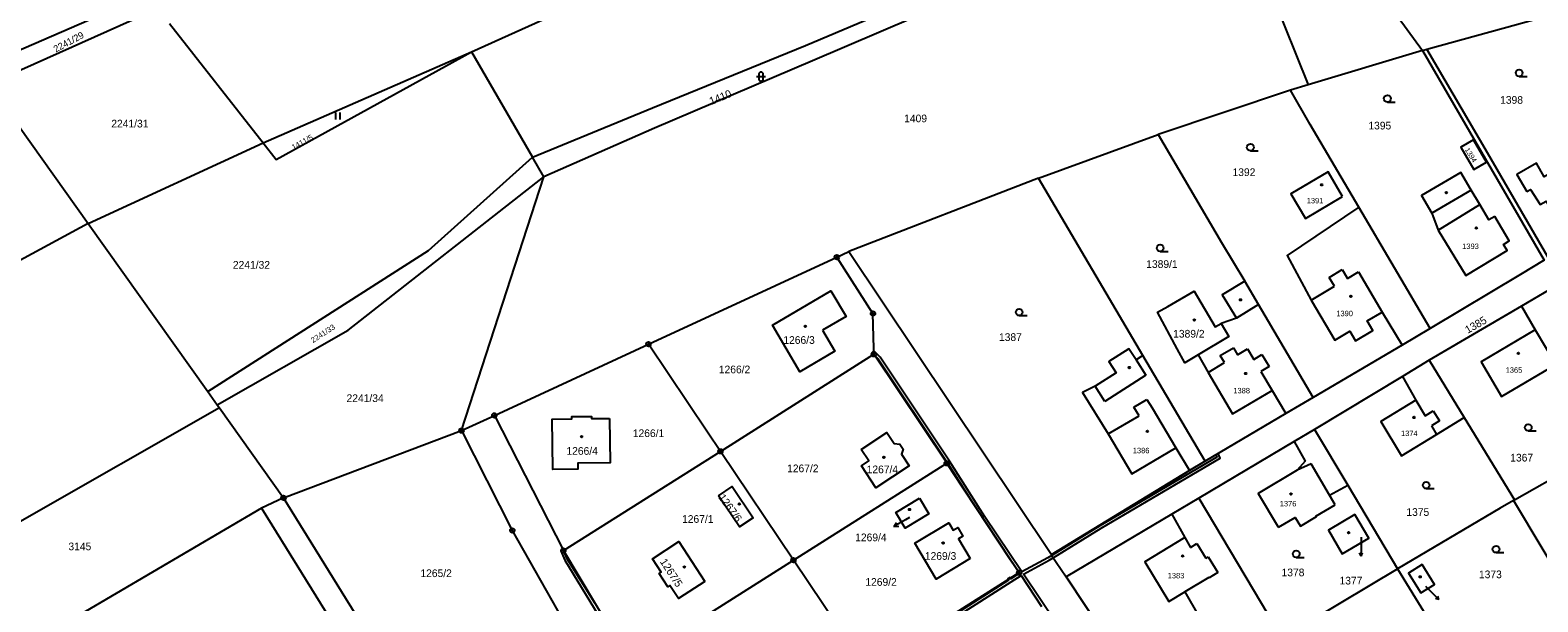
# Model space of a CAD drawing. Extents: x -504988 to -494607, y -1123820 to -1114018.
# Drawn here: x -498445.5 to -498111.8, y -1119267 to -1119140.5 of the extents above; entities that cross this region are included whole.
import ezdxf

# ---------------------------------------------------------------- set-up
doc = ezdxf.new("R2010")
doc.units = 0
for name, color, linetype in [('Hranice parcel', 7, 'Continuous'), ('Parcelní čísla', 7, 'Continuous'), ('Pop  PČ popisy', 7, 'Continuous'), ('Vnitřní kresba', 7, 'Continuous'), ('Věcná břemena k části', 7, 'Continuous'), ('Značky bodu BP', 7, 'Continuous'), ('Značky budov', 7, 'Continuous'), ('Značky kultur', 7, 'Continuous')]:
    doc.layers.add(name, color=color, linetype=linetype)

msp = doc.modelspace()

# ---------------------------------------------------------------- linework, layer by layer
at = {"layer": 'Hranice parcel'}
for p, q in [((-498176.47, -1119118.03), (-498162.61, -1119152.61)), ((-498157.48, -1119117.49), (-498137.28, -1119144.99)), ((-498419.61, -1119132.7), (-498457.09, -1119149)), ((-498454.64, -1119152.44), (-498417.24, -1119135.72)), ((-498414.66, -1119139.01), (-498393.92, -1119165.45)), ((-498136.33, -1119144.7), (-498111.4, -1119137.86)), ((-498393.92, -1119165.45), (-498347.84, -1119145.3)), ((-498347.84, -1119145.3), (-498334.3, -1119168.63)), ((-498137.28, -1119144.99), (-498162.61, -1119152.61)), ((-498137.28, -1119144.99), (-498136.33, -1119144.7)), ((-498454.64, -1119152.44), (-498432.67, -1119183.28)), ((-498166.51, -1119153.79), (-498195.79, -1119163.6)), ((-498162.61, -1119152.61), (-498166.51, -1119153.79)), ((-498222.34, -1119173.27), (-498195.79, -1119163.6)), ((-498432.67, -1119183.28), (-498393.92, -1119165.45)), ((-498331.79, -1119172.96), (-498334.3, -1119168.63)), ((-498350.01, -1119229.11), (-498331.79, -1119172.96)), ((-498222.34, -1119173.27), (-498264.28, -1119189.49)), ((-498199.2, -1119212.51), (-498222.34, -1119173.27)), ((-498135.6, -1119206.51), (-498151.42, -1119179.68)), ((-498432.67, -1119183.28), (-498406.17, -1119220.48)), ((-498266.95, -1119190.72), (-498264.28, -1119189.49)), ((-498308.62, -1119209.98), (-498266.95, -1119190.72)), ((-498258.94, -1119203.22), (-498266.95, -1119190.72)), ((-498109.12, -1119197.88), (-498115.41, -1119201.58)), ((-498115.41, -1119201.58), (-498135.81, -1119213.56)), ((-498135.6, -1119206.51), (-498141.8, -1119210.18)), ((-498342.74, -1119225.75), (-498308.62, -1119209.98)), ((-498141.8, -1119210.18), (-498161.49, -1119221.82)), ((-498292.71, -1119233.7), (-498258.74, -1119212.23)), ((-498242.62, -1119236.35), (-498258.74, -1119212.23)), ((-498185.45, -1119235.85), (-498199.2, -1119212.51)), ((-498135.81, -1119213.56), (-498141.77, -1119217.14)), ((-498135.81, -1119213.56), (-498128.09, -1119226.19)), ((-498141.77, -1119217.14), (-498161.24, -1119228.84)), ((-498406.17, -1119220.48), (-498404.1, -1119223.38)), ((-498404.1, -1119223.38), (-498403.59, -1119224.1)), ((-498161.49, -1119221.82), (-498167.53, -1119225.36)), ((-498403.59, -1119224.1), (-498389.42, -1119243.99)), ((-498350.01, -1119229.11), (-498342.74, -1119225.75)), ((-498342.74, -1119225.75), (-498327.47, -1119255.66)), ((-498167.53, -1119225.36), (-498185.45, -1119235.85)), ((-498128.09, -1119226.19), (-498116.93, -1119244.45)), ((-498389.42, -1119243.99), (-498350.01, -1119229.11)), ((-498161.24, -1119228.84), (-498165.72, -1119231.5)), ((-498161.24, -1119228.84), (-498153.87, -1119241.2)), ((-498327.47, -1119255.66), (-498292.71, -1119233.7)), ((-498276.55, -1119257.79), (-498292.71, -1119233.7)), ((-498165.72, -1119231.5), (-498186.82, -1119244.07)), ((-498276.55, -1119257.79), (-498242.62, -1119236.35)), ((-498185.45, -1119235.85), (-498188.86, -1119237.93)), ((-498116.93, -1119244.45), (-498104.11, -1119237.11)), ((-498188.86, -1119237.93), (-498219.49, -1119256.58)), ((-498153.87, -1119241.2), (-498142.82, -1119259.73)), ((-498394.29, -1119246.3), (-498477.41, -1119294.96)), ((-498389.42, -1119243.99), (-498394.29, -1119246.3)), ((-498394.29, -1119246.3), (-498375.52, -1119276.48)), ((-498360.07, -1119291.3), (-498389.42, -1119243.99)), ((-498186.82, -1119244.07), (-498192.79, -1119247.61)), ((-498186.82, -1119244.07), (-498169.68, -1119272.79)), ((-498116.93, -1119244.45), (-498117.19, -1119244.61)), ((-498117.19, -1119244.61), (-498098.47, -1119275.83)), ((-498192.79, -1119247.61), (-498216.21, -1119261.47)), ((-498219.49, -1119256.58), (-498216.21, -1119261.47)), ((-498312.55, -1119280.54), (-498276.55, -1119257.79)), ((-498168.4, -1119274.94), (-498142.82, -1119259.73)), ((-498142.82, -1119259.73), (-498133.3, -1119275.24)), ((-498216.21, -1119261.47), (-498196.16, -1119291.56))]:
    msp.add_line(p, q, dxfattribs=at)
for points in [[(-498347.84, -1119145.3), (-498307.68, -1119127.2), (-498226.19, -1119098.54), (-498200.12, -1119089.51)], [(-498334.3, -1119168.63), (-498307.73, -1119157.69), (-498273.85, -1119143.89), (-498220.78, -1119121.39), (-498189.63, -1119116.18)], [(-498176.47, -1119118.03), (-498188.44, -1119118.94), (-498220.2, -1119124.93), (-498272.34, -1119147.33), (-498307.3, -1119162.21), (-498331.79, -1119172.96)], [(-498393.92, -1119165.45), (-498391.06, -1119169.1), (-498347.84, -1119145.3)], [(-498137.28, -1119144.99), (-498110.37, -1119191.37), (-498115.64, -1119194.57), (-498135.6, -1119206.51)], [(-498087.55, -1119177.87), (-498109.51, -1119190.84), (-498122.93, -1119167.67), (-498136.33, -1119144.7)], [(-498151.42, -1119179.68), (-498162.19, -1119161.42), (-498166.51, -1119153.79)], [(-498195.79, -1119163.6), (-498181.78, -1119187.48), (-498176.65, -1119196.07)], [(-498123.17, -1119169.72), (-498126.02, -1119164.81), (-498128.8, -1119166.42), (-498125.95, -1119171.34), (-498123.17, -1119169.72)], [(-498406.17, -1119220.48), (-498357.36, -1119189.26), (-498334.3, -1119168.63)], [(-498114.25, -1119176.23), (-498113.43, -1119175.76), (-498111.24, -1119179.09), (-498109.97, -1119178.33), (-498106.89, -1119183.53), (-498098.66, -1119178.66), (-498104.13, -1119169.37), (-498110.38, -1119172.93), (-498112.07, -1119169.96), (-498116.41, -1119172.43), (-498114.25, -1119176.23)], [(-498404.1, -1119223.38), (-498375.11, -1119206.88), (-498331.79, -1119172.96)], [(-498154.99, -1119177.33), (-498158.18, -1119171.89), (-498166.42, -1119176.73), (-498163.22, -1119182.16), (-498154.99, -1119177.33)], [(-498121.31, -1119181.74), (-498122.6, -1119182.5), (-498124.6, -1119179.1), (-498126.55, -1119175.93), (-498128.85, -1119171.99), (-498137.56, -1119177.06), (-498135.26, -1119181), (-498133.88, -1119184.74), (-498127.74, -1119194.78), (-498118.6, -1119189.3), (-498119.42, -1119187.91), (-498118.13, -1119187.15), (-498121.31, -1119181.74)], [(-498151.42, -1119179.68), (-498167.29, -1119190.35), (-498161.98, -1119200.24), (-498156.72, -1119209.1), (-498153.4, -1119207.14), (-498152.14, -1119209.27), (-498148.29, -1119207), (-498149.56, -1119204.86), (-498146.23, -1119202.89), (-498141.8, -1119210.18)], [(-498432.67, -1119183.28), (-498599.02, -1119273.35), (-498667.99, -1119331.88), (-498738.66, -1119434), (-498809.33, -1119536.13), (-498929.21, -1119599.31)], [(-498264.28, -1119189.49), (-498219.6, -1119256.32), (-498219.49, -1119256.58)], [(-498176.65, -1119196.07), (-498181.64, -1119199.09), (-498178.51, -1119204.27), (-498181.88, -1119205.43)], [(-498161.49, -1119221.82), (-498173.59, -1119201.21), (-498176.65, -1119196.07)], [(-498270.12, -1119206.9), (-498267.37, -1119211.56), (-498275.16, -1119216.08), (-498281.21, -1119205.75), (-498268.27, -1119198.19), (-498264.91, -1119203.9), (-498270.12, -1119206.9)], [(-498186.93, -1119212.34), (-498189.92, -1119214.13), (-498191.63, -1119211.02), (-498195.94, -1119202.94), (-498193.68, -1119201.66), (-498187.84, -1119198.24), (-498183.2, -1119206.17), (-498181.88, -1119205.43)], [(-498258.74, -1119212.23), (-498258.77, -1119210.96), (-498258.94, -1119203.22)], [(-498115.41, -1119201.58), (-498112.37, -1119206.82), (-498124.35, -1119213.92), (-498119.8, -1119221.59), (-498107.82, -1119214.5), (-498105.78, -1119213.05), (-498106.4, -1119212.03), (-498103.25, -1119210.13), (-498102.16, -1119209.6)], [(-498181.88, -1119205.43), (-498180.18, -1119208.28), (-498186.93, -1119212.34)], [(-498292.71, -1119233.7), (-498295.55, -1119229.46), (-498308.62, -1119209.98)], [(-498199.2, -1119212.51), (-498200.7, -1119213.47), (-498202.3, -1119210.99), (-498206.73, -1119213.85), (-498205.13, -1119216.33), (-498209.76, -1119219.31), (-498212.55, -1119220.67), (-498206.87, -1119229.86), (-498201.63, -1119238.68), (-498191.94, -1119232.92), (-498188.86, -1119237.93)], [(-498186.93, -1119212.34), (-498184.78, -1119216.23), (-498179.34, -1119225.4), (-498170.59, -1119220.21), (-498167.53, -1119225.36)], [(-498141.77, -1119217.14), (-498138.78, -1119222.41), (-498146.53, -1119227.13), (-498141.94, -1119234.69), (-498134.18, -1119229.98), (-498128.09, -1119226.19)], [(-498403.59, -1119224.1), (-498492.01, -1119274.49), (-498477.41, -1119294.96)], [(-498317.25, -1119226.42), (-498317.15, -1119236.26), (-498324.29, -1119236.35), (-498324.27, -1119237.65), (-498329.8, -1119237.73), (-498329.93, -1119226.58), (-498325.59, -1119226.53), (-498325.59, -1119226.02), (-498321.25, -1119225.98), (-498321.24, -1119226.47), (-498317.25, -1119226.42)], [(-498350.01, -1119229.11), (-498338.78, -1119251.2), (-498327.52, -1119271.11)], [(-498261.55, -1119233.32), (-498255.84, -1119229.52), (-498254.23, -1119231.94), (-498252.99, -1119232.14), (-498252.29, -1119233.2), (-498252.62, -1119234.36), (-498250.94, -1119236.89), (-498258.29, -1119241.79), (-498261.51, -1119236.89), (-498259.88, -1119235.82), (-498261.55, -1119233.32)], [(-498165.72, -1119231.5), (-498163.27, -1119235.88), (-498165.08, -1119237.88), (-498173.68, -1119243.04), (-498169.39, -1119250.2), (-498169.19, -1119250.51)], [(-498228.47, -1119257.7), (-498241.27, -1119238.4), (-498242.62, -1119236.35)], [(-498293.15, -1119243.55), (-498290.11, -1119241.5), (-498285.47, -1119248.39), (-498288.5, -1119250.43), (-498293.15, -1119243.55)], [(-498156.63, -1119245.5), (-498157.89, -1119243.36), (-498153.87, -1119241.2)], [(-498248.66, -1119244.09), (-498246.58, -1119247.53), (-498251.85, -1119250.71), (-498253.9, -1119247.24), (-498248.66, -1119244.09)], [(-498169.19, -1119250.51), (-498165.46, -1119248.36), (-498164.32, -1119250.25), (-498160.8, -1119248.15), (-498160.89, -1119248.03), (-498156.63, -1119245.5)], [(-498117.19, -1119244.61), (-498120.09, -1119246.31), (-498142.82, -1119259.73)], [(-498237.41, -1119257.41), (-498244.94, -1119261.95), (-498249.69, -1119254.04), (-498242.14, -1119249.52), (-498241.16, -1119251.14), (-498240.17, -1119250.55), (-498239.04, -1119252.44), (-498240.03, -1119253.03), (-498237.41, -1119257.41)], [(-498192.79, -1119247.61), (-498189.94, -1119252.78), (-498198.77, -1119258.13), (-498193.44, -1119266.93), (-498189.9, -1119264.78), (-498183.54, -1119275.82), (-498181.57, -1119279.25), (-498175.12, -1119275.54), (-498169.68, -1119272.79)], [(-498152.28, -1119247.68), (-498158.14, -1119251.16), (-498155.06, -1119256.36), (-498149.2, -1119252.89), (-498152.28, -1119247.68)], [(-498296.13, -1119262.47), (-498302.02, -1119266.29), (-498303.94, -1119263.4), (-498304.36, -1119263.67), (-498306.29, -1119260.7), (-498305.86, -1119260.43), (-498307.77, -1119257.52), (-498301.89, -1119253.65), (-498296.13, -1119262.47)], [(-498327.47, -1119255.66), (-498320.46, -1119267.36), (-498314.23, -1119277.75), (-498312.55, -1119280.54)], [(-498260.39, -1119281.88), (-498263.13, -1119277.8), (-498276.55, -1119257.79)], [(-498260.39, -1119281.88), (-498226.6, -1119260.53), (-498228.47, -1119257.7)], [(-498137.36, -1119258.77), (-498140.41, -1119260.66), (-498137.71, -1119265.01), (-498134.67, -1119263.13), (-498137.36, -1119258.77)]]:
    msp.add_lwpolyline(points, dxfattribs=at)
at = {"layer": 'Pop  PČ popisy'}
for p, q in [((-498251.74, -1119248.85), (-498254.34, -1119250.35)), ((-498254.34, -1119250.35), (-498253.72, -1119249.42)), ((-498254.34, -1119250.35), (-498253.22, -1119250.28)), ((-498250.83, -1119248.32), (-498251.74, -1119248.85)), ((-498150.91, -1119252.68), (-498150.91, -1119254.78)), ((-498150.91, -1119256.88), (-498151.26, -1119256.18)), ((-498150.91, -1119254.78), (-498150.91, -1119256.88)), ((-498150.91, -1119256.88), (-498150.56, -1119256.18)), ((-498136.65, -1119263.51), (-498135.16, -1119264.99)), ((-498135.16, -1119264.99), (-498133.67, -1119266.48)), ((-498133.67, -1119266.48), (-498134.42, -1119266.23)), ((-498133.67, -1119266.48), (-498133.92, -1119265.73))]:
    msp.add_line(p, q, dxfattribs=at)
at = {"layer": 'Vnitřní kresba'}
for p, q in [((-498126.55, -1119175.93), (-498135.26, -1119181)), ((-498133.88, -1119184.74), (-498124.6, -1119179.1)), ((-498157.95, -1119195.22), (-498155.1, -1119193.48)), ((-498155.1, -1119193.48), (-498153.93, -1119195.46)), ((-498161.98, -1119200.24), (-498156.79, -1119197.16)), ((-498156.79, -1119197.16), (-498157.95, -1119195.22)), ((-498153.93, -1119195.46), (-498151.49, -1119194.02)), ((-498151.49, -1119194.02), (-498146.23, -1119202.89)), ((-498173.59, -1119201.21), (-498178.51, -1119204.27)), ((-498112.37, -1119206.82), (-498107.82, -1119214.5)), ((-498200.7, -1119213.47), (-498198.53, -1119216.83)), ((-498182.07, -1119212.5), (-498179.17, -1119210.78)), ((-498181.14, -1119214.07), (-498182.07, -1119212.5)), ((-498179.17, -1119210.78), (-498178.24, -1119212.34)), ((-498178.24, -1119212.34), (-498176.03, -1119211.03)), ((-498176.03, -1119211.03), (-498174.65, -1119213.36)), ((-498174.65, -1119213.36), (-498172.86, -1119212.29)), ((-498172.86, -1119212.29), (-498171.28, -1119214.95)), ((-498198.53, -1119216.83), (-498207.6, -1119222.67)), ((-498184.78, -1119216.23), (-498181.14, -1119214.07)), ((-498171.28, -1119214.95), (-498173.07, -1119216.02)), ((-498173.07, -1119216.02), (-498170.59, -1119220.21)), ((-498207.6, -1119222.67), (-498209.76, -1119219.31)), ((-498201.18, -1119223.92), (-498198.3, -1119222.2)), ((-498200.05, -1119225.82), (-498201.18, -1119223.92)), ((-498198.3, -1119222.2), (-498197.17, -1119224.11)), ((-498138.78, -1119222.41), (-498136.7, -1119225.83)), ((-498206.87, -1119229.86), (-498200.05, -1119225.82)), ((-498197.17, -1119224.11), (-498191.94, -1119232.92)), ((-498136.7, -1119225.83), (-498134.92, -1119224.75)), ((-498133.57, -1119226.98), (-498135.34, -1119228.06)), ((-498134.92, -1119224.75), (-498133.57, -1119226.98)), ((-498135.34, -1119228.06), (-498134.18, -1119229.98)), ((-498161.95, -1119236.43), (-498165.08, -1119237.88)), ((-498157.89, -1119243.36), (-498161.95, -1119236.43)), ((-498189.94, -1119252.78), (-498188.63, -1119254.95)), ((-498188.63, -1119254.95), (-498187.23, -1119254.1)), ((-498187.23, -1119254.1), (-498185.25, -1119257.37)), ((-498185.25, -1119257.37), (-498184.73, -1119257.05)), ((-498184.73, -1119257.05), (-498182.62, -1119260.54)), ((-498182.62, -1119260.54), (-498184.54, -1119261.71)), ((-498184.61, -1119261.59), (-498189.9, -1119264.78)), ((-498184.54, -1119261.71), (-498184.61, -1119261.59))]:
    msp.add_line(p, q, dxfattribs=at)
at = {"layer": 'Věcná břemena k části'}
for points in [[(-498211.17, -1119282.43), (-498225.65, -1119260.88), (-498219.92, -1119257.78), (-498219.05, -1119257.24), (-498208.44, -1119250.71), (-498182.09, -1119235.22), (-498182.54, -1119234.15), (-498183.06, -1119234.45), (-498182.85, -1119234.96), (-498208.74, -1119250.19), (-498219.38, -1119256.74), (-498220.22, -1119257.26), (-498225.98, -1119260.38), (-498234.18, -1119248.2), (-498242, -1119235.84), (-498257.32, -1119212.88), (-498258.76, -1119211.47), (-498258.74, -1119212.23), (-498257.78, -1119213.26), (-498242.69, -1119235.88), (-498242.88, -1119235.96), (-498242.62, -1119236.35), (-498242.54, -1119236.47), (-498242.36, -1119236.38), (-498237.28, -1119244.41), (-498228.47, -1119257.7), (-498226.6, -1119260.53), (-498226.5, -1119260.68), (-498228.42, -1119261.91), (-498228.53, -1119261.75), (-498229.04, -1119262.07), (-498228.93, -1119262.23), (-498260.26, -1119282.24)], [(-498320.46, -1119267.36), (-498326.63, -1119257.5), (-498327.31, -1119255.92), (-498327.47, -1119255.66), (-498327.61, -1119255.38), (-498328.01, -1119255.75), (-498327.17, -1119257.78), (-498319.76, -1119269.84)], [(-498259.94, -1119282.74), (-498228.36, -1119262.58), (-498226.17, -1119261.18), (-498221.61, -1119268.02)]]:
    msp.add_lwpolyline(points, dxfattribs=at)
for points in [[(-498258.76, -1119211.47), (-498259.13, -1119211.95), (-498258.74, -1119212.23)], [(-498242.99, -1119236.02), (-498242.78, -1119236.45), (-498242.62, -1119236.35), (-498242.88, -1119235.96)], [(-498242.62, -1119236.35), (-498242.78, -1119236.45), (-498242.73, -1119236.56), (-498242.54, -1119236.47)], [(-498327.47, -1119255.66), (-498327.31, -1119255.92), (-498327.07, -1119255.7), (-498327.23, -1119255.51)], [(-498229.04, -1119262.07), (-498228.53, -1119261.75), (-498228.61, -1119261.62), (-498229.12, -1119261.94)]]:
    msp.add_lwpolyline(points, close=True, dxfattribs=at)
at = {"layer": 'Značky bodu BP'}
for centre, radius in [((-498266.95, -1119190.72), 0.5), ((-498266.95, -1119190.72), 0.0303), ((-498258.94, -1119203.22), 0.5), ((-498258.94, -1119203.22), 0.0303), ((-498308.62, -1119209.98), 0.5), ((-498308.62, -1119209.98), 0.0303), ((-498258.74, -1119212.23), 0.5), ((-498258.74, -1119212.23), 0.0303), ((-498342.74, -1119225.75), 0.5), ((-498342.74, -1119225.75), 0.0303), ((-498350.01, -1119229.11), 0.5), ((-498350.01, -1119229.11), 0.0303), ((-498292.71, -1119233.7), 0.5), ((-498292.71, -1119233.7), 0.0303), ((-498242.62, -1119236.35), 0.5), ((-498242.62, -1119236.35), 0.0303), ((-498389.42, -1119243.99), 0.5), ((-498389.42, -1119243.99), 0.0303), ((-498338.78, -1119251.2), 0.5), ((-498338.78, -1119251.2), 0.0303), ((-498327.47, -1119255.66), 0.5), ((-498327.47, -1119255.66), 0.0303), ((-498276.55, -1119257.79), 0.5), ((-498276.55, -1119257.79), 0.0303), ((-498226.6, -1119260.53), 0.5), ((-498226.6, -1119260.53), 0.0303)]:
    msp.add_circle(centre, radius, dxfattribs=at)
at = {"layer": 'Značky budov'}
for centre in [(-498159.65, -1119174.73), (-498132.06, -1119176.49), (-498125.4, -1119184.27), (-498177.6, -1119200.17), (-498153.17, -1119199.41), (-498273.92, -1119206.06), (-498187.83, -1119204.66), (-498116.09, -1119212), (-498202.22, -1119215.16), (-498176.45, -1119216.47), (-498139.18, -1119226.2), (-498323.42, -1119230.46), (-498198.21, -1119229.26), (-498256.53, -1119235.03), (-498166.43, -1119243.16), (-498288.53, -1119245.35), (-498250.85, -1119246.57), (-498243.42, -1119253.99), (-498153.67, -1119251.69), (-498190.39, -1119256.85), (-498300.69, -1119259.3), (-498137.82, -1119261.47)]:
    msp.add_circle(centre, 0.175, dxfattribs=at)
at = {"layer": 'Značky kultur'}
for p, q in [((-498284.24, -1119150.28), (-498284.24, -1119151.28)), ((-498283.24, -1119151.28), (-498283.24, -1119150.28)), ((-498284.74, -1119150.78), (-498282.74, -1119150.78)), ((-498115.91, -1119150.74), (-498114.16, -1119150.74)), ((-498145.09, -1119156.42), (-498143.34, -1119156.42)), ((-498377.85, -1119160.25), (-498377.85, -1119158.75)), ((-498376.85, -1119160.25), (-498376.85, -1119158.75)), ((-498175.41, -1119167.2), (-498173.66, -1119167.2)), ((-498195.37, -1119189.47), (-498193.62, -1119189.47)), ((-498226.59, -1119203.68), (-498224.84, -1119203.68)), ((-498113.91, -1119229.18), (-498112.16, -1119229.18)), ((-498136.5, -1119241.95), (-498134.75, -1119241.95)), ((-498165.26, -1119257.16), (-498163.51, -1119257.16)), ((-498121.04, -1119256.11), (-498119.29, -1119256.11))]:
    msp.add_line(p, q, dxfattribs=at)
for centre in [(-498115.91, -1119149.99), (-498145.09, -1119155.67), (-498175.41, -1119166.45), (-498195.37, -1119188.72), (-498226.59, -1119202.93), (-498113.91, -1119228.43), (-498136.5, -1119241.2), (-498165.26, -1119256.41), (-498121.04, -1119255.36)]:
    msp.add_circle(centre, 0.75, dxfattribs=at)
for centre, start, end in [((-498283.74, -1119150.28), 0, 180), ((-498283.74, -1119151.28), 180, 359.9879)]:
    msp.add_arc(centre, 0.5, start, end, dxfattribs=at)

# ---------------------------------------------------------------- texts
at = {"layer": 'Parcelní čísla'}
for s, height, rotation, p in [('2241/29', 1.5, 28, (-498439.83, -1119145.48)), ('1410', 1.7, 22, (-498294.76, -1119157.09)), ('1411/5', 1.2, 29, (-498387.19, -1119167.04)), ('1394', 1.139, 302, (-498128, -1119166.96)), ('1385', 1.7, 30, (-498127.29, -1119207.71)), ('2241/33', 1.2, 33, (-498382.88, -1119209.76)), ('1267/6', 1.7, 306, (-498293.26, -1119243.9)), ('1267/5', 1.7, 303, (-498306.17, -1119258.11))]:
    msp.add_text(s, height=height, rotation=rotation, dxfattribs=at).set_placement(p)
for s, height, p in [('1398', 1.7, (-498120.13, -1119156.8)), ('2241/31', 1.7, (-498427.53, -1119162.04)), ('1409', 1.7, (-498252.04, -1119160.89)), ('1395', 1.7, (-498149.29, -1119162.48)), ('1392', 1.7, (-498179.36, -1119172.79)), ('1391', 1.2, (-498162.94, -1119178.83)), ('1393', 1.2, (-498128.53, -1119188.93)), ('2241/32', 1.7, (-498400.62, -1119193.29)), ('1389/1', 1.7, (-498198.46, -1119193.12)), ('1390', 1.2, (-498156.39, -1119203.8)), ('1389/2', 1.7, (-498192.5, -1119208.53)), ('1266/3', 1.7, (-498278.78, -1119209.92)), ('1387', 1.7, (-498231.05, -1119209.27)), ('1266/2', 1.7, (-498293.06, -1119216.43)), ('1365', 1.2, (-498118.91, -1119216.32)), ('1388', 1.2, (-498179.18, -1119220.86)), ('2241/34', 1.7, (-498375.46, -1119222.79)), ('1266/1', 1.7, (-498312.1, -1119230.54)), ('1374', 1.2, (-498142.07, -1119230.32)), ('1266/4', 1.7, (-498326.79, -1119234.46)), ('1386', 1.2, (-498201.43, -1119234.12)), ('1267/2', 1.7, (-498277.95, -1119238.32)), ('1267/4', 1.7, (-498260.34, -1119238.55)), ('1367', 1.7, (-498117.89, -1119235.95)), ('1376', 1.2, (-498168.91, -1119245.88)), ('1375', 1.7, (-498140.88, -1119247.98)), ('1267/1', 1.7, (-498301.2, -1119249.52)), ('3145', 1.7, (-498437.02, -1119255.59)), ('1269/4', 1.7, (-498262.88, -1119253.59)), ('1269/3', 1.7, (-498247.46, -1119257.7)), ('1265/2', 1.7, (-498359.11, -1119261.52)), ('1383', 1.2, (-498193.71, -1119261.8)), ('1378', 1.7, (-498168.51, -1119261.34)), ('1373', 1.7, (-498124.82, -1119261.77)), ('1269/2', 1.7, (-498260.63, -1119263.45)), ('1377', 1.7, (-498155.68, -1119263.16))]:
    msp.add_text(s, height=height, dxfattribs=at).set_placement(p)

doc.saveas('drawing.dxf')
